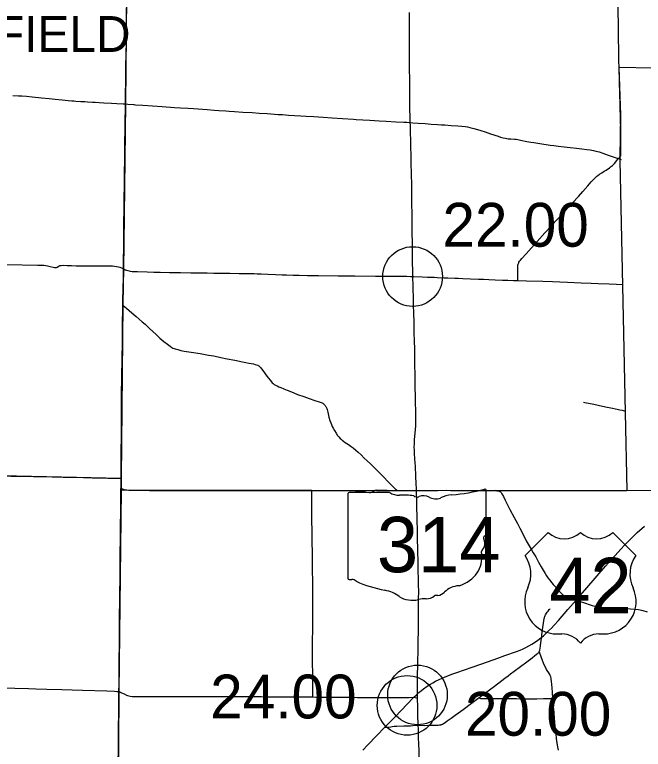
# Model space of a CAD drawing. Extents: x 1813937 to 1948437, y 826606 to 1022856.
# Drawn here: x 1913070 to 1928879, y 954153 to 972609 of the extents above; entities that cross this region are included whole.
import ezdxf

# ---------------------------------------------------------------- set-up
doc = ezdxf.new("R2010")
doc.units = 0
for name, color, linetype in [('Default', 7, 'Continuous'), ('GM_X_County', 7, 'Continuous'), ('GM_X_County_Road', 7, 'Continuous'), ('GM_X_State_Route', 7, 'Continuous'), ('GM_X_State_Shield', 7, 'Continuous'), ('GM_X_Township', 7, 'Continuous'), ('GM_X_Township_Road', 7, 'Continuous'), ('GM_X_Township_Text', 7, 'Continuous'), ('GM_X_US_Route', 7, 'Continuous'), ('GM_X_US_Shield', 7, 'Continuous')]:
    doc.layers.add(name, color=color, linetype=linetype)

msp = doc.modelspace()

# ---------------------------------------------------------------- linework, layer by layer
at = {"layer": 'Default'}
for centre in [(1923078, 966031), (1923200, 955519), (1922938, 955256)]:
    msp.add_circle(centre, 750, dxfattribs=at)
at = {"layer": 'GM_X_County'}
msp.add_lwpolyline([(1929986, 971246), (1928265, 971283), (1928303, 970087), (1928288, 969028), (1928289, 968947), (1928357, 965797), (1928425, 962614), (1928467, 960653), (1930020, 960674)], dxfattribs=at)
at = {"layer": 'GM_X_County_Road'}
for points in [[(1912869, 966331), (1913655, 966320), (1913753, 966319), (1913802, 966316), (1913851, 966311), (1913899, 966302), (1913963, 966285), (1914042, 966263), (1914074, 966256), (1914090, 966255), (1914106, 966256), (1914122, 966260), (1914137, 966267), (1914178, 966294), (1914193, 966301), (1914208, 966307), (1914224, 966310), (1914240, 966312), (1914289, 966313), (1914387, 966309), (1914502, 966306), (1914617, 966303), (1914731, 966302), (1914830, 966301), (1915010, 966299), (1915174, 966298), (1915321, 966299), (1915469, 966299), (1915534, 966296), (1915583, 966292), (1915632, 966285), (1915680, 966274), (1915711, 966265), (1915757, 966247), (1915770, 966242), (1915789, 966232), (1915807, 966222)], [(1915807, 966222), (1915822, 966213), (1915838, 966203), (1915859, 966195), (1915881, 966188), (1915913, 966179), (1915978, 966167), (1916027, 966160), (1916076, 966156), (1916158, 966153), (1916404, 966148), (1916568, 966143), (1916732, 966140), (1916962, 966135), (1917125, 966131), (1917199, 966129)], [(1917199, 966129), (1917240, 966129), (1917504, 966127), (1917911, 966121), (1918075, 966119), (1918276, 966117), (1918478, 966114), (1918714, 966110), (1918845, 966109), (1918894, 966108), (1918943, 966108), (1919091, 966106), (1919172, 966102), (1919271, 966099), (1919435, 966092), (1919631, 966082), (1919795, 966075), (1919909, 966072), (1920073, 966067), (1920221, 966064), (1920434, 966060), (1920708, 966058), (1921206, 966052), (1921628, 966050), (1922140, 966044), (1922370, 966041), (1922567, 966039), (1922731, 966037), (1922928, 966037), (1923026, 966034), (1923085, 966030)], [(1923085, 966030), (1923108, 966029), (1923321, 966023), (1923452, 966017), (1923616, 966011), (1923698, 966009), (1923862, 966002), (1923960, 965996), (1924140, 965990), (1924222, 965987), (1924337, 965982), (1924534, 965974), (1924730, 965966), (1924862, 965961), (1924993, 965956), (1925157, 965950), (1925337, 965942), (1925468, 965938), (1925616, 965933), (1925725, 965931)], [(1925725, 965931), (1925730, 965931), (1925944, 965924), (1926354, 965912), (1926599, 965902), (1926779, 965895), (1926975, 965887), (1927320, 965876), (1927567, 965866), (1927745, 965858), (1928024, 965846), (1928202, 965838), (1928360, 965834)], [(1926905, 958007), (1926971, 957977), (1927027, 957956), (1927097, 957932), (1927163, 957909), (1927188, 957902)], [(1927188, 957902), (1927222, 957892), (1927268, 957876), (1927423, 957823), (1927517, 957792), (1927595, 957768), (1927660, 957752), (1927708, 957742), (1927773, 957732), (1927838, 957725), (1927953, 957716), (1928221, 957701), (1928560, 957686), (1928674, 957677), (1928755, 957665), (1928803, 957656), (1928867, 957641), (1928977, 957610)], [(1926324, 956971), (1926326, 956995), (1926329, 957027), (1926343, 957156), (1926376, 957379), (1926387, 957442), (1926391, 957458), (1926395, 957473), (1926400, 957488), (1926414, 957518), (1926421, 957532), (1926446, 957574), (1926464, 957601), (1926483, 957626), (1926515, 957662), (1926526, 957674), (1926536, 957687)], [(1926256, 956606), (1926259, 956610), (1926266, 956624), (1926273, 956638), (1926278, 956653), (1926286, 956684), (1926296, 956749), (1926313, 956895), (1926324, 956971)], [(1924739, 955445), (1924848, 955527), (1925137, 955743), (1925321, 955880), (1925399, 955940), (1925476, 956000), (1925542, 956049), (1925635, 956116), (1925791, 956234), (1925949, 956350), (1926080, 956448), (1926145, 956498), (1926195, 956539), (1926219, 956561), (1926231, 956572), (1926241, 956584), (1926250, 956597), (1926256, 956606)], [(1910463, 955791), (1910484, 955790), (1910927, 955773), (1912123, 955726), (1912336, 955718), (1913073, 955691), (1913418, 955680), (1913598, 955675), (1913877, 955666), (1914254, 955655), (1914778, 955638), (1915384, 955619), (1915581, 955611), (1915640, 955608), (1915667, 955604), (1915693, 955599)], [(1915670, 952967), (1915670, 952983), (1915670, 953098), (1915673, 953312), (1915675, 953525), (1915676, 953755), (1915681, 954215), (1915682, 954412), (1915683, 954576), (1915683, 954707), (1915686, 955036), (1915690, 955266), (1915691, 955430), (1915693, 955551), (1915693, 955599)], [(1915693, 955599), (1915712, 955594), (1915725, 955590), (1915743, 955582), (1915759, 955574), (1915820, 955544), (1915879, 955516), (1915910, 955504), (1915941, 955495), (1915973, 955489), (1916022, 955483), (1916071, 955481), (1916252, 955480), (1916465, 955480), (1917399, 955481), (1918202, 955479), (1918350, 955479), (1918513, 955478), (1918661, 955477), (1918759, 955477), (1918874, 955476), (1919005, 955477), (1919267, 955476), (1919431, 955473), (1919595, 955472), (1919710, 955472), (1919792, 955472), (1919955, 955472), (1920086, 955471), (1920299, 955469), (1920398, 955469), (1920545, 955467), (1920567, 955467)], [(1920567, 955467), (1920643, 955465), (1920807, 955464), (1921069, 955463), (1921233, 955462), (1921405, 955460)], [(1921405, 955460), (1921413, 955460), (1921544, 955459), (1921692, 955458), (1921889, 955456), (1922003, 955453), (1922118, 955454), (1922281, 955455), (1922380, 955454), (1922560, 955453), (1922675, 955452), (1922773, 955452), (1922921, 955455), (1922993, 955457), (1923107, 955459)], [(1923107, 955459), (1923142, 955453), (1923178, 955443), (1923201, 955436)], [(1923217, 954757), (1923377, 954755), (1923475, 954757), (1923557, 954759), (1923655, 954760), (1923720, 954762), (1923752, 954765), (1923768, 954767), (1923784, 954770), (1923799, 954774), (1923815, 954780), (1923829, 954786), (1923857, 954801), (1923898, 954829), (1923950, 954869), (1924043, 954935), (1924150, 955011), (1924230, 955068), (1924348, 955156), (1924559, 955312), (1924717, 955429), (1924739, 955445)], [(1922380, 954706), (1922426, 954705), (1922480, 954711), (1922528, 954721), (1922564, 954728), (1922612, 954731), (1922677, 954734), (1922855, 954739), (1922936, 954740), (1923020, 954745), (1923085, 954750), (1923178, 954756), (1923217, 954757)]]:
    msp.add_lwpolyline(points, dxfattribs=at)
at = {"layer": 'GM_X_State_Route'}
for points in [[(1923199, 955548), (1923199, 955574), (1923198, 955607), (1923198, 955706), (1923200, 955820), (1923201, 955918), (1923202, 956000), (1923207, 956279), (1923210, 956427), (1923213, 956558), (1923217, 956788), (1923218, 956919), (1923222, 957083), (1923227, 957395), (1923228, 957576), (1923229, 957904), (1923230, 958134), (1923229, 958265), (1923226, 958429), (1923219, 958643), (1923217, 958790), (1923214, 958889), (1923210, 959102), (1923201, 959513), (1923196, 959710), (1923192, 959857), (1923191, 959939), (1923185, 960284), (1923181, 960448), (1923179, 960581), (1923174, 960652), (1923172, 960696), (1923169, 960827), (1923162, 961008), (1923157, 961106), (1923153, 961172), (1923147, 961270), (1923142, 961352), (1923135, 961450), (1923126, 961581), (1923121, 961679), (1923120, 961744), (1923122, 961826), (1923128, 961924), (1923152, 962185), (1923158, 962283), (1923160, 962382), (1923159, 962513), (1923154, 962710), (1923152, 962808), (1923148, 963022), (1923142, 963251), (1923140, 963399), (1923140, 963547), (1923134, 963826), (1923130, 964055), (1923130, 964154), (1923122, 964465), (1923120, 964563), (1923117, 964744), (1923114, 964892), (1923106, 965105), (1923102, 965318), (1923098, 965449), (1923091, 965777), (1923085, 966030), (1923083, 966089), (1923075, 966466), (1923071, 966663), (1923063, 967352), (1923063, 967549), (1923063, 967630), (1923062, 967663), (1923060, 967795), (1923058, 967926), (1923057, 968090), (1923055, 968320), (1923054, 968402), (1923051, 968533), (1923050, 968648), (1923045, 968845), (1923043, 968927), (1923037, 969123), (1923034, 969238), (1923029, 969418), (1923024, 969681), (1923021, 969829), (1923019, 969899), (1923015, 970042), (1923011, 970239), (1923009, 970468), (1923008, 970583), (1923008, 970714), (1923006, 970829), (1923005, 971059), (1923003, 971174), (1923002, 971239), (1923002, 971305), (1923002, 971452), (1923002, 971534), (1923000, 971649), (1922998, 971780), (1922997, 971928), (1922997, 972026), (1922999, 972223), (1922995, 972666)], [(1923255, 953496), (1923252, 953597), (1923246, 953843), (1923239, 954106), (1923232, 954302), (1923228, 954433), (1923226, 954515), (1923222, 954679), (1923219, 954744), (1923217, 954757), (1923217, 954825), (1923212, 954972), (1923208, 955102), (1923207, 955195), (1923207, 955247), (1923206, 955282), (1923204, 955361), (1923201, 955436), (1923201, 955460), (1923199, 955525), (1923199, 955548)]]:
    msp.add_lwpolyline(points, dxfattribs=at)
at = {"layer": 'GM_X_State_Shield'}
for p, q in [((1921447, 960565), (1921447, 958452)), ((1922500, 960601), (1921481, 960601)), ((1924927, 959548), (1924927, 960654)), ((1924927, 959549), (1924927, 959548))]:
    msp.add_line(p, q, dxfattribs=at)
for centre, major_axis, start_param, end_param in [((1923688, 963483), (3691, 0), 4.814394, 5.042369), ((1924889, 960658), (38.7, 0), 6.141152, 7.989035), ((1921487, 960570), (40.3, 0), 1.712693, 3.28349), ((1922743, 960847), (391, 0), 4.042523, 4.731795), ((1922873, 959415), (1404, 0), 1.404758, 1.657858), ((1923192, 960581), (113, 0), 3.836095, 5.185415), ((1923357, 960336), (235, 0), 0.950623, 2.079405), ((1923660, 960671), (282, 0), 4.081561, 5.145723), ((1924158, 959956), (743, 0), 1.699011, 2.107814), ((1924918, 959467), (60, 0), 1.883978, 3.671073), ((1924537, 959327), (360, 0), 5.934695, 6.695948), ((1924886, 959544), (41.5, 0), 5.05454, 6.418171), ((1925066, 959086), (262, 0), 2.387724, 3.262537), ((1923894, 958945), (923, 0), 5.101752, 6.440018), ((1921487, 958447), (40.7, 0), 3.00124, 4.508301), ((1921493, 958663), (310, 0), 4.665946, 4.897461), ((1921557, 958330), (112, 0), 0.519207, 1.627899), ((1922970, 960229), (2665, 0), 4.195997, 4.488961), ((1922175, 957502), (834, 0), 0.823519, 1.323587), ((1923643, 958247), (298, 0), 4.937069, 5.64225), ((1924284, 957859), (506, 0), 1.647645, 2.488434), ((1923077, 958319), (529, 0), 4.026481, 4.996735), ((1923383, 957589), (435, 0), 1.495662, 1.94098), ((1923422, 958161), (282, 0), 4.691044, 5.507374), ((1923677, 957956), (79.4, 0), 1.147584, 2.315152)]:
    msp.add_ellipse(centre, major_axis=major_axis, ratio=0.8, start_param=start_param, end_param=end_param, dxfattribs=at)
at = {"layer": 'GM_X_Township'}
for points in [[(1916031, 987559), (1916031, 987390), (1916016, 983574), (1916012, 983206), (1915968, 979502), (1915954, 977797), (1915930, 976934), (1915938, 976821), (1915894, 974189), (1915874, 972112), (1915857, 970374), (1915816, 966860), (1915806, 966233), (1915788, 965343), (1915744, 960965)], [(1889423, 961536), (1894728, 961453), (1894730, 961440), (1894815, 961451), (1899962, 961375), (1907847, 961159), (1910485, 961083), (1915744, 960965), (1915744, 960672), (1915689, 955598), (1915669, 952972), (1915640, 948490), (1915630, 947868), (1915624, 947610), (1915561, 944982), (1915495, 939674)], [(1915744, 960672), (1915744, 960965)], [(1915744, 960672), (1920541, 960662), (1921738, 960652), (1922124, 960663), (1922164, 960668), (1922719, 960651), (1923180, 960652), (1925154, 960663), (1925224, 960656), (1928467, 960653), (1930020, 960674), (1933801, 960656)]]:
    msp.add_lwpolyline(points, dxfattribs=at)
at = {"layer": 'GM_X_Township_Road'}
for points in [[(1915876, 971659), (1915877, 971687), (1915878, 971868), (1915882, 972048), (1915882, 972147), (1915882, 972311), (1915884, 972442), (1915886, 972622), (1915890, 972950), (1915893, 973492), (1915895, 973754), (1915898, 973934), (1915899, 974033), (1915900, 974115), (1915901, 974182)], [(1928272, 971231), (1928267, 971504), (1928267, 971592), (1928263, 971739), (1928261, 971820), (1928258, 971918), (1928256, 972131), (1928254, 972246), (1928251, 972393), (1928247, 972656), (1928244, 972787), (1928240, 972967), (1928239, 973082), (1928236, 973229), (1928232, 973475), (1928228, 973787), (1928226, 973903)], [(1915857, 970366), (1915857, 970443), (1915858, 970525), (1915861, 970721), (1915862, 970819), (1915864, 970918), (1915865, 971000), (1915867, 971081), (1915869, 971196), (1915869, 971261), (1915869, 971343), (1915875, 971589), (1915876, 971659)], [(1928282, 970925), (1928280, 970985), (1928272, 971231)], [(1928295, 970413), (1928292, 970574), (1928289, 970688), (1928284, 970852), (1928282, 970925)], [(1913023, 970580), (1913170, 970573), (1913252, 970568), (1913367, 970560), (1913514, 970546), (1913742, 970523), (1913938, 970503), (1914085, 970488), (1914264, 970470), (1914412, 970455), (1914509, 970447), (1914557, 970443), (1914606, 970439), (1914736, 970431), (1914834, 970425), (1914900, 970421), (1915030, 970412), (1915096, 970408), (1915194, 970403), (1915309, 970398), (1915505, 970387), (1915636, 970381), (1915799, 970371), (1915857, 970366)], [(1915807, 966222), (1915806, 966230), (1915806, 966361), (1915809, 966509), (1915811, 966689), (1915814, 966820), (1915816, 966935), (1915818, 967131), (1915818, 967328), (1915819, 967426), (1915820, 967655), (1915823, 967787), (1915827, 968049), (1915829, 968262), (1915832, 968426), (1915833, 968524), (1915835, 968721), (1915838, 968885), (1915839, 969049), (1915841, 969213), (1915844, 969459), (1915848, 969656), (1915850, 969836), (1915852, 970049), (1915854, 970148), (1915857, 970279), (1915858, 970361), (1915857, 970366)], [(1915857, 970366), (1915913, 970363), (1916060, 970352), (1916076, 970350), (1916109, 970347), (1916289, 970334), (1916781, 970300), (1917092, 970278), (1917239, 970268), (1917435, 970257), (1917567, 970250), (1917910, 970226), (1918090, 970212), (1918205, 970205), (1918384, 970192), (1918466, 970187), (1918597, 970179), (1918810, 970164), (1919039, 970152), (1919219, 970138), (1919416, 970124), (1919694, 970105), (1919809, 970098), (1919956, 970088), (1920103, 970078), (1920267, 970067), (1920398, 970060), (1920595, 970048), (1920824, 970032), (1921053, 970018), (1921315, 970002), (1921593, 969983), (1921659, 969980), (1921823, 969970), (1922003, 969960), (1922232, 969946), (1922412, 969935), (1922658, 969920), (1922854, 969910), (1922936, 969905), (1923019, 969899)], [(1928304, 970054), (1928302, 970100), (1928299, 970198), (1928296, 970312), (1928295, 970413)], [(1923019, 969899), (1923083, 969894), (1923214, 969886), (1923394, 969873), (1923542, 969862), (1923705, 969851), (1923804, 969844), (1923885, 969839), (1924049, 969829), (1924213, 969817), (1924314, 969809), (1924395, 969799), (1924458, 969788), (1924520, 969774), (1924615, 969749), (1924711, 969723), (1924790, 969700), (1924900, 969666), (1925040, 969619), (1925226, 969555), (1925289, 969536), (1925352, 969519), (1925416, 969505), (1925481, 969494), (1925547, 969488), (1925643, 969482), (1925684, 969480), (1925720, 969473), (1925791, 969458), (1925953, 969426), (1926049, 969408), (1926128, 969394), (1926274, 969371), (1926533, 969334), (1926631, 969321), (1926745, 969306), (1926892, 969290), (1927038, 969273), (1927201, 969254), (1927332, 969239), (1927462, 969223), (1927543, 969212), (1927624, 969198), (1927688, 969184), (1927767, 969164), (1927860, 969133), (1927999, 969083), (1928199, 969011), (1928253, 968993)], [(1928312, 969067), (1928311, 969249), (1928310, 969430), (1928311, 969528), (1928312, 969659), (1928311, 969708), (1928311, 969790), (1928309, 969920), (1928304, 970054)], [(1925725, 965931), (1925725, 965969), (1925723, 966084), (1925720, 966199), (1925721, 966248), (1925723, 966281), (1925727, 966313), (1925735, 966345), (1925740, 966361), (1925745, 966376), (1925752, 966391), (1925769, 966419), (1925788, 966445), (1925820, 966483), (1925930, 966604), (1926206, 966907), (1926403, 967125), (1926491, 967223), (1926579, 967320), (1926712, 967464), (1926845, 967609), (1927000, 967777), (1927100, 967885), (1927245, 968040), (1927354, 968163), (1927484, 968310), (1927569, 968409), (1927624, 968469), (1927682, 968527), (1927706, 968549), (1927732, 968569), (1927775, 968599), (1927832, 968635), (1927897, 968676), (1927941, 968702), (1928032, 968764), (1928057, 968784), (1928103, 968821), (1928123, 968839), (1928155, 968874), (1928186, 968910), (1928207, 968936), (1928248, 968986), (1928253, 968993)], [(1928253, 968993), (1928285, 969031), (1928312, 969067)], [(1928253, 968993), (1928285, 968984), (1928323, 968969)], [(1915790, 965307), (1915790, 965312), (1915794, 965542), (1915796, 965607), (1915797, 965673), (1915798, 965754), (1915803, 965968), (1915807, 966132), (1915807, 966222)], [(1915744, 960960), (1915744, 960987), (1915745, 961085), (1915745, 961151), (1915746, 961298), (1915748, 961380), (1915750, 961528), (1915752, 961708), (1915754, 961937), (1915755, 962036), (1915755, 962134), (1915755, 962249), (1915757, 962478), (1915757, 962592), (1915758, 962789), (1915759, 962969), (1915760, 963248), (1915761, 963314), (1915763, 963428), (1915764, 963477), (1915765, 963559), (1915770, 963903), (1915773, 964001), (1915779, 964329), (1915780, 964443), (1915783, 964631), (1915785, 964804), (1915785, 964952), (1915786, 965116), (1915788, 965198), (1915790, 965307)], [(1915790, 965307), (1915828, 965279), (1915842, 965269), (1915880, 965238), (1916017, 965121), (1916129, 965025), (1916278, 964896), (1916351, 964830), (1916459, 964729), (1916628, 964574), (1916724, 964485), (1916774, 964442), (1916824, 964400), (1916913, 964328), (1916979, 964279), (1917019, 964251), (1917048, 964235), (1917078, 964222), (1917109, 964211), (1917172, 964194), (1917251, 964175), (1917332, 964159), (1917510, 964129), (1917737, 964094), (1917947, 964059), (1918076, 964035), (1918253, 964000), (1918414, 963967), (1918606, 963926), (1918798, 963886), (1918879, 963870), (1918959, 963856), (1919072, 963834), (1919120, 963823), (1919151, 963813), (1919181, 963800), (1919196, 963792), (1919210, 963783), (1919223, 963773), (1919235, 963763), (1919258, 963739), (1919279, 963714), (1919308, 963674), (1919414, 963528), (1919494, 963424), (1919525, 963386), (1919548, 963362), (1919572, 963341), (1919599, 963321), (1919626, 963304), (1919670, 963281), (1919714, 963260), (1919760, 963240), (1919835, 963209), (1919926, 963172), (1919987, 963150), (1920094, 963108), (1920185, 963071), (1920339, 963013), (1920478, 962963), (1920618, 962917), (1920728, 962884), (1920775, 962868), (1920804, 962855), (1920818, 962846), (1920832, 962837), (1920844, 962826), (1920856, 962815), (1920867, 962803), (1920878, 962790), (1920887, 962777), (1920896, 962763), (1920903, 962748), (1920916, 962718), (1920926, 962687), (1920942, 962623), (1920974, 962496), (1920998, 962417), (1921019, 962355), (1921036, 962310), (1921057, 962265), (1921079, 962222), (1921112, 962165), (1921155, 962095), (1921192, 962041), (1921222, 962002), (1921254, 961965), (1921277, 961942), (1921302, 961920), (1921341, 961891), (1921382, 961863), (1921465, 961810), (1921532, 961764), (1921585, 961725), (1921648, 961672), (1921709, 961618), (1921780, 961550), (1921863, 961470), (1921933, 961402), (1922015, 961322), (1922051, 961288), (1922134, 961209), (1922169, 961175), (1922285, 961059), (1922319, 961024), (1922491, 960848), (1922617, 960719), (1922648, 960689), (1922662, 960677), (1922674, 960668), (1922689, 960659), (1922702, 960652)], [(1927375, 962872), (1927407, 962866), (1927632, 962822), (1927856, 962776), (1927968, 962752), (1928063, 962731), (1928223, 962696), (1928287, 962683), (1928351, 962670), (1928428, 962652)], [(1910489, 961081), (1910686, 961075), (1911095, 961063), (1911390, 961055), (1911522, 961051), (1911620, 961050), (1911751, 961048), (1911833, 961046), (1912178, 961037), (1912604, 961030), (1912982, 961019), (1913140, 961016)], [(1913140, 961016), (1913324, 961014), (1913543, 961010), (1914015, 960998), (1914113, 960995), (1914293, 960991), (1914557, 960986), (1914801, 960980), (1915015, 960975), (1915196, 960971), (1915409, 960968), (1915541, 960965), (1915714, 960961), (1915744, 960960)], [(1915744, 960960), (1915743, 960855), (1915741, 960757), (1915741, 960707)], [(1915717, 958184), (1915719, 958332), (1915719, 958480), (1915719, 958611), (1915720, 958725), (1915723, 958873), (1915725, 959004), (1915726, 959152), (1915728, 959348), (1915729, 959430), (1915730, 959561), (1915734, 959872), (1915736, 960003), (1915737, 960184), (1915738, 960364), (1915739, 960479), (1915740, 960577), (1915741, 960707)], [(1915741, 960707), (1915757, 960702), (1915824, 960681), (1915856, 960675), (1915889, 960671), (1915938, 960667), (1916036, 960664), (1916266, 960660), (1916464, 960657), (1916806, 960657), (1916939, 960657), (1917053, 960658), (1917300, 960656), (1917512, 960656), (1917759, 960653), (1918054, 960651), (1918217, 960653), (1918349, 960653), (1918481, 960653), (1918659, 960653), (1918804, 960652), (1918924, 960653), (1919056, 960652), (1919185, 960653), (1919364, 960657), (1919579, 960658), (1919745, 960656), (1919908, 960655), (1920085, 960658), (1920318, 960657), (1920515, 960658), (1920539, 960658)], [(1920539, 960658), (1920597, 960657), (1920743, 960657), (1920890, 960655), (1921165, 960652), (1921348, 960651), (1921459, 960651), (1921642, 960649), (1921760, 960646), (1921810, 960644), (1921825, 960642)], [(1920558, 959102), (1920556, 959163), (1920554, 959294), (1920552, 959474), (1920549, 959638), (1920545, 959900), (1920543, 960080), (1920541, 960358), (1920540, 960506), (1920539, 960604), (1920539, 960639), (1920539, 960658)], [(1921825, 960642), (1921842, 960640), (1921874, 960634), (1921937, 960617), (1921970, 960609), (1921986, 960607), (1922002, 960606), (1922018, 960607), (1922034, 960611), (1922049, 960618), (1922076, 960634), (1922091, 960643)], [(1922091, 960643), (1922103, 960650), (1922117, 960656), (1922131, 960659), (1922152, 960660), (1922176, 960659), (1922221, 960659), (1922352, 960656), (1922549, 960654), (1922702, 960652)], [(1922702, 960652), (1922779, 960651), (1923006, 960652), (1923154, 960652), (1923174, 960652)], [(1923174, 960652), (1923303, 960654), (1923510, 960654), (1923711, 960657), (1923925, 960661), (1924034, 960658), (1924197, 960656), (1924286, 960656), (1924465, 960653), (1924597, 960651), (1924779, 960652), (1924927, 960654), (1925058, 960653), (1925173, 960651), (1925194, 960649)], [(1925194, 960649), (1925205, 960648), (1925238, 960643), (1925254, 960638), (1925269, 960633), (1925284, 960625), (1925296, 960615), (1925306, 960602), (1925323, 960574), (1925360, 960501), (1925405, 960413), (1925524, 960179), (1925629, 959975), (1925715, 959822), (1925776, 959707), (1925882, 959498), (1925935, 959394), (1926008, 959265), (1926059, 959181), (1926112, 959092), (1926174, 958985), (1926246, 958856), (1926311, 958739), (1926408, 958571), (1926442, 958515), (1926480, 958461), (1926520, 958408), (1926582, 958332), (1926614, 958295), (1926646, 958258), (1926709, 958182), (1926776, 958108), (1926812, 958074), (1926835, 958054), (1926859, 958034), (1926905, 958007)], [(1920566, 957271), (1920567, 957313), (1920567, 957411), (1920569, 957640), (1920569, 957722), (1920568, 957837), (1920566, 958082), (1920565, 958246), (1920564, 958443), (1920562, 958574), (1920560, 958688), (1920560, 958803), (1920560, 958934), (1920559, 959065), (1920558, 959102)], [(1915693, 955599), (1915692, 955652), (1915694, 955741), (1915694, 955856), (1915695, 956069), (1915697, 956200), (1915699, 956463), (1915702, 956725), (1915704, 957004), (1915705, 957168), (1915709, 957413), (1915710, 957593), (1915712, 957791), (1915716, 957938), (1915716, 958070), (1915717, 958184)], [(1920565, 955995), (1920565, 956086), (1920563, 956299), (1920561, 956397), (1920560, 956512), (1920559, 956659), (1920561, 956806), (1920563, 956921), (1920564, 957117), (1920565, 957199), (1920566, 957271)], [(1926600, 955426), (1926600, 955436), (1926591, 955584), (1926583, 955698), (1926570, 955862), (1926564, 955910), (1926558, 955942), (1926550, 955973), (1926539, 956004), (1926526, 956033), (1926501, 956075), (1926465, 956130), (1926448, 956157), (1926424, 956201), (1926394, 956259), (1926367, 956319), (1926345, 956381), (1926312, 956476), (1926276, 956565), (1926256, 956606)], [(1920567, 955467), (1920567, 955497), (1920567, 955710), (1920566, 955824), (1920565, 955995)], [(1924739, 955445), (1924767, 955437), (1924781, 955432), (1924787, 955431), (1924794, 955430), (1925041, 955433), (1925305, 955430), (1925689, 955426), (1925843, 955422), (1925986, 955423), (1926200, 955425), (1926368, 955426), (1926569, 955426), (1926600, 955426)], [(1926743, 954134), (1926727, 954214), (1926711, 954311), (1926698, 954425), (1926685, 954539), (1926673, 954653), (1926664, 954734), (1926645, 954930), (1926634, 955077), (1926607, 955355), (1926600, 955426)]]:
    msp.add_lwpolyline(points, dxfattribs=at)
at = {"layer": 'GM_X_US_Route'}
for points in [[(1924091, 956045), (1924186, 956079), (1924573, 956215), (1924790, 956292), (1924959, 956353), (1925223, 956444), (1925393, 956506), (1925686, 956611), (1925778, 956646), (1925854, 956679), (1925928, 956714), (1926000, 956752), (1926072, 956794), (1926141, 956838), (1926222, 956894), (1926301, 956953), (1926324, 956971), (1926365, 957005), (1926426, 957059), (1926498, 957127), (1926567, 957198), (1926634, 957270), (1926743, 957393), (1926981, 957664), (1927188, 957902), (1927228, 957949), (1927457, 958207), (1927932, 958750), (1928082, 958924), (1928159, 959010), (1928323, 959193), (1928401, 959277), (1928538, 959418), (1928620, 959498), (1928728, 959598), (1928911, 959763)], [(1921829, 954134), (1921955, 954263), (1922170, 954489), (1922380, 954706), (1922478, 954807), (1922638, 954972), (1923093, 955445), (1923107, 955459), (1923163, 955515), (1923199, 955548), (1923211, 955559), (1923299, 955632), (1923351, 955672), (1923445, 955738), (1923527, 955792), (1923583, 955825), (1923655, 955864), (1923743, 955908), (1923818, 955942), (1923893, 955972), (1924091, 956045)]]:
    msp.add_lwpolyline(points, dxfattribs=at)
at = {"layer": 'GM_X_US_Shield'}
for p, q in [((1926484, 959603), (1925904, 959023)), ((1928689, 959023), (1928109, 959603)), ((1926716, 957051), (1926832, 957051)), ((1927761, 957051), (1927877, 957051))]:
    msp.add_line(p, q, dxfattribs=at)
for centre, radius, start, end in [((1926890, 960017), 580, 225.573, 314.427), ((1927703, 960017), 580, 225.573, 314.427), ((1925239, 958557), 812, 334.5471, 35.0009), ((1929354, 958557), 812, 144.9991, 205.4529), ((1926707, 957863), 812, 154.8319, 270.6383), ((1927886, 957863), 812, 269.3617, 25.1681), ((1926832, 956471), 580, 36.8699, 90), ((1927761, 956471), 580, 90, 143.1301)]:
    msp.add_arc(centre, radius, start, end, dxfattribs=at)

# ---------------------------------------------------------------- texts
at = {"layer": 'Default'}
for s, p in [('22.00', (1923827, 966781)), ('24.00', (1917987, 954929)), ('20.00', (1924393, 954495))]:
    msp.add_text(s, height=1100, dxfattribs=at).set_placement(p)
at = {"layer": 'GM_X_State_Shield'}
msp.add_text('314', height=1392.2, dxfattribs=at).set_placement((1922181, 958601))
at = {"layer": 'GM_X_Township_Text'}
msp.add_text('BLOOMFIELD', height=900, rotation=0, dxfattribs=at).set_placement((1908226, 971674))
at = {"layer": 'GM_X_US_Shield'}
msp.add_text('42', height=1392.2, dxfattribs=at).set_placement((1926513, 957573))

doc.saveas('drawing.dxf')
